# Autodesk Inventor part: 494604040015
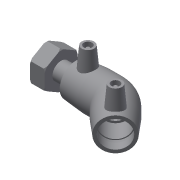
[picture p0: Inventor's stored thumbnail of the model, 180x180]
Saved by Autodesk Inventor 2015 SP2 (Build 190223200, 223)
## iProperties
Created: 2017-06
Part Number: 494604040015
Material: Generic
Description: PLASSON 45° ELBOW FEMALE FREE NUT TRANSITION 40-1.1/2"
Document SubType Name: Modeling
Designer: KIM
Mass: 55.0731 g
Surface Area: 148.067 cm^2
Volume: 55.0731 cm^3
Density: 1 g/cm^3
Appearance: Default
Author: KIM
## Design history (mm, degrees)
derived "494604.ipt"
feature "Solid1::494604.ipt"
tag "TaggingFeature1"
body "Solid1"
other parameters: "d2" = 56, "d4" = 27, "d5" = 50.4, "d8" = 168 deg, "d10" = 17.6, "d11" = 5.86667, "d29" = 47, "d30" = 15, "d31" = 37.8, "d34" = 5 deg, "d41" = 4, "d42" = 14, "d43" = 0, "d50" = 34, "d51" = 17.6, "d52" = 44.44, "d54" = 135 deg, "d86" = 25.2, "d87" = 135 deg, "d88" = 108, "d90" = 44, "d91" = 0, "d92" = 44, "d93" = 0, "d101" = 3, "d102" = 0, "d108" = 29, "d110" = 38, "d112" = 67.2675, "d113" = 44.845, "d139" = 31.3915, "d140" = 29, "d141" = 19, "d142" = 1.9, "d143" = 3.8, "d144" = 15.2, "d145" = 35.876, "d146" = 2.24225, "d150" = 0, "d151" = 2, "L_" = 146, "L_1" = 44, "D_" = 29, "A_" = 47, "d_2" = 12, "L_2" = 38, "G_" = 44.845, "D_1" = 56
